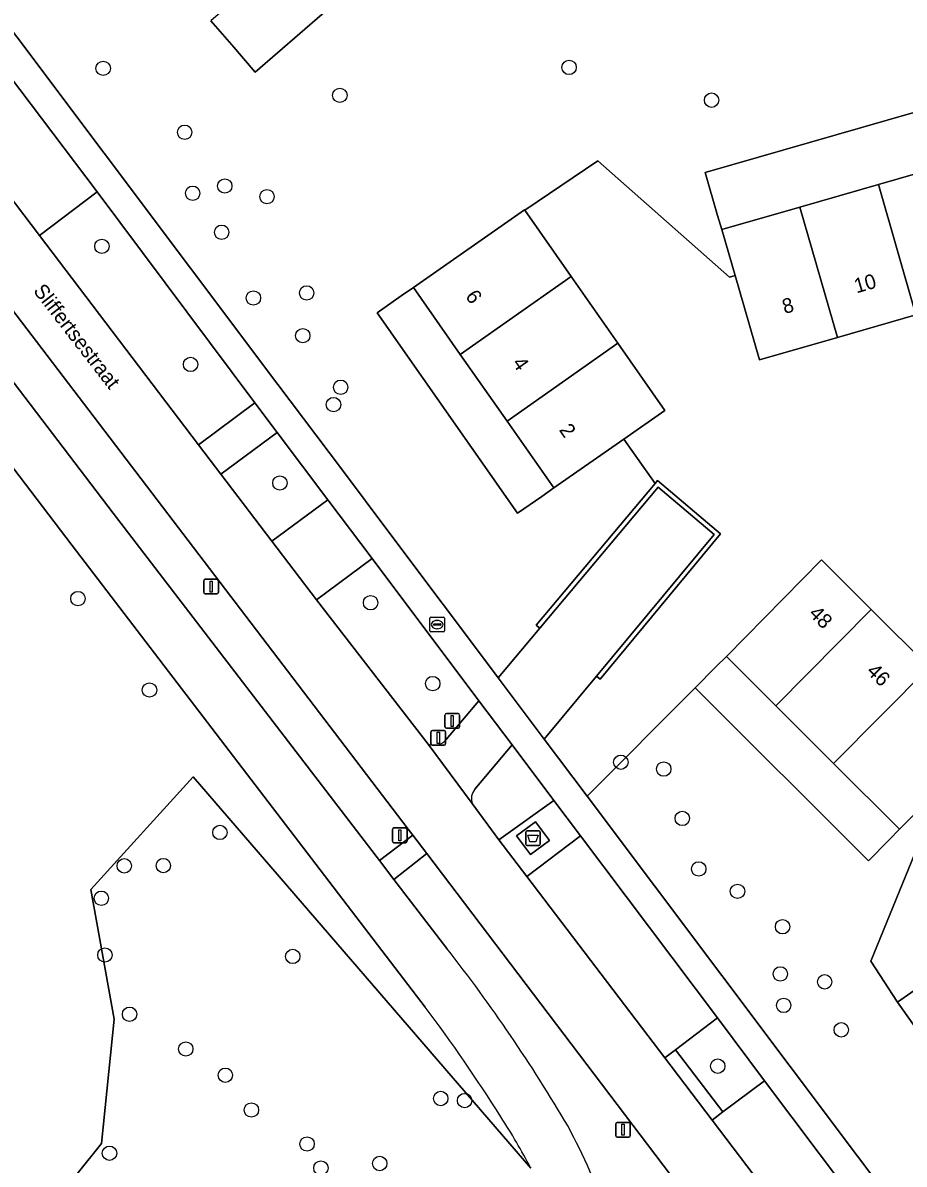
# Model space of a CAD drawing. Extents: x 156661 to 157576, y 383570 to 384425.
# Drawn here: x 156921.7 to 156981.6, y 384130.7 to 384208.3 of the extents above; entities that cross this region are included whole.
import ezdxf

# ---------------------------------------------------------------- set-up
doc = ezdxf.new("R2010")
doc.units = 0
for name, color, linetype in [('IMGEO_Afsluitpaal', 7, 'Continuous'), ('IMGEO_Afval_apart_plaats', 7, 'Continuous'), ('IMGEO_Berm_groen', 7, 'Continuous'), ('IMGEO_Berm_open', 7, 'Continuous'), ('IMGEO_Boom', 7, 'Continuous'), ('IMGEO_Brandkraan', 7, 'Continuous'), ('IMGEO_Erf', 7, 'Continuous'), ('IMGEO_Fietspad_gesloten', 7, 'Continuous'), ('IMGEO_Fietspad_open', 7, 'Continuous'), ('IMGEO_Groenvoorziening', 7, 'Continuous'), ('IMGEO_Lichtmast', 7, 'Continuous'), ('IMGEO_Muur', 7, 'Continuous'), ('IMGEO_Naaldbos', 7, 'Continuous'), ('IMGEO_Openbare_ruimte_label', 7, 'Continuous'), ('IMGEO_Pand', 7, 'Continuous'), ('IMGEO_Pand_nummerreeks', 7, 'Continuous'), ('IMGEO_Parkeervlak_open', 7, 'Continuous'), ('IMGEO_Rijbaan_lokaal_gesloten', 7, 'Continuous'), ('IMGEO_Rijbaan_lokaal_open', 7, 'Continuous'), ('IMGEO_Voetpad_gesloten', 7, 'Continuous'), ('IMGEO_Voetpad_open', 7, 'Continuous')]:
    doc.layers.add(name, color=color, linetype=linetype)

msp = doc.modelspace()

# ---------------------------------------------------------------- linework, layer by layer
at = {"layer": 'IMGEO_Afsluitpaal'}
for p, q in [((156950.378, 384160.425), (156950.378, 384161.225)), ((156950.378, 384161.225), (156950.378, 384160.425)), ((156950.478, 384161.325), (156951.268, 384161.325)), ((156951.268, 384161.325), (156950.478, 384161.325)), ((156951.368, 384161.225), (156951.368, 384160.425)), ((156951.368, 384160.425), (156951.368, 384161.225)), ((156949.428, 384159.276), (156949.428, 384160.076)), ((156949.428, 384160.076), (156949.428, 384159.276)), ((156949.528, 384160.176), (156950.318, 384160.176)), ((156950.318, 384160.176), (156949.528, 384160.176)), ((156950.418, 384160.076), (156950.418, 384159.276)), ((156950.418, 384159.276), (156950.418, 384160.076)), ((156951.268, 384160.325), (156950.478, 384160.325)), ((156950.478, 384160.325), (156951.268, 384160.325)), ((156950.318, 384159.176), (156949.528, 384159.176)), ((156949.528, 384159.176), (156950.318, 384159.176))]:
    msp.add_line(p, q, dxfattribs=at)
for points in [[(156950.798, 384161.2), (156950.948, 384161.2), (156950.948, 384160.45), (156950.798, 384160.45), (156950.798, 384161.2)], [(156949.848, 384160.051), (156949.998, 384160.051), (156949.998, 384159.301), (156949.848, 384159.301), (156949.848, 384160.051)]]:
    msp.add_lwpolyline(points, dxfattribs=at)
for centre, start, end in [((156950.478, 384161.225), 90, 180), ((156950.478, 384161.225), 90, 180), ((156951.268, 384161.225), 0, 90), ((156951.268, 384161.225), 360, 90), ((156949.528, 384160.076), 90, 180), ((156949.528, 384160.076), 90, 180), ((156950.318, 384160.076), 0, 90), ((156950.318, 384160.076), 360, 90), ((156950.478, 384160.425), 180, 270), ((156950.478, 384160.425), 180, 270), ((156951.268, 384160.425), 270, 0), ((156951.268, 384160.425), 270, 0), ((156949.528, 384159.276), 180, 270), ((156949.528, 384159.276), 180, 270), ((156950.318, 384159.276), 270, 0), ((156950.318, 384159.276), 270, 0)]:
    msp.add_arc(centre, 0.1, start, end, dxfattribs=at)
at = {"layer": 'IMGEO_Afval_apart_plaats'}
for p, q in [((156955.87, 384152.455), (156955.87, 384153.255)), ((156955.87, 384153.255), (156955.87, 384152.455)), ((156955.97, 384153.355), (156956.76, 384153.355)), ((156956.76, 384153.355), (156955.97, 384153.355)), ((156956.86, 384153.255), (156956.86, 384152.455)), ((156956.86, 384152.455), (156956.86, 384153.255)), ((156956.76, 384152.355), (156955.97, 384152.355)), ((156955.97, 384152.355), (156956.76, 384152.355))]:
    msp.add_line(p, q, dxfattribs=at)
msp.add_lwpolyline([(156956.013, 384153.069), (156956.717, 384153.069), (156956.568, 384152.599), (156956.162, 384152.599), (156956.013, 384153.069)], dxfattribs=at)
for centre, start, end in [((156955.97, 384153.255), 90, 180), ((156955.97, 384153.255), 90, 180), ((156956.76, 384153.255), 0, 90), ((156956.76, 384153.255), 360, 90), ((156955.97, 384152.455), 180, 270), ((156955.97, 384152.455), 180, 270), ((156956.76, 384152.455), 270, 0), ((156956.76, 384152.455), 270, 0)]:
    msp.add_arc(centre, 0.1, start, end, dxfattribs=at)
at = {"layer": 'IMGEO_Berm_groen'}
for points in [[(156867.867, 384253.653), (156927.81, 384174.952), (156945.927, 384151.336), (156948.198, 384153.058), (156947.883, 384153.474), (156869.636, 384256.091)], [(156945.427, 384171.858), (156941.651, 384169.047), (156949.248, 384159.24)], [(156950.46, 384159.552), (156952.69, 384162.198), (156945.427, 384171.858)], [(156949.137, 384151.82), (156946.909, 384150.056), (156950.51, 384145.361)], [(156967.768, 384127.243), (156949.137, 384151.82)]]:
    msp.add_lwpolyline(points, dxfattribs=at)
for points in [[(156926.719, 384196.787), (156922.806, 384193.826), (156933.628, 384179.594), (156937.458, 384182.455)], [(156938.971, 384180.443), (156935.139, 384177.608), (156938.611, 384173.044), (156942.416, 384175.861)], [(156968.907, 384140.631), (156966.06, 384138.467), (156969.272, 384134.245), (156972.116, 384136.364)]]:
    msp.add_lwpolyline(points, close=True, dxfattribs=at)
for centre, radius, start, end in [((156949.643, 384160.215), 1.052, 247.92674, 320.94521), ((156863.016, 384076.914), 111.087, 30.48417, 38.03635), ((156914.405, 384109.729), 50.202, 20.20282, 27.96194)]:
    msp.add_arc(centre, radius, start, end, dxfattribs=at)
at = {"layer": 'IMGEO_Berm_open'}
for points in [[(156952.237, 384155.208), (156954.053, 384152.742), (156957.791, 384155.414), (156954.942, 384159.203)], [(156954.942, 384159.203), (156952.419, 384156.18)]]:
    msp.add_lwpolyline(points, dxfattribs=at)
msp.add_lwpolyline([(156966.06, 384138.467), (156965.332, 384137.913), (156968.544, 384133.691), (156969.272, 384134.245)], close=True, dxfattribs=at)
msp.add_arc((156953.136, 384155.543), 0.959, 138.35735, 200.43181, dxfattribs=at)
at = {"layer": 'IMGEO_Boom'}
for centre in [(156927.137, 384205.187), (156958.823, 384205.253), (156943.231, 384203.351), (156968.508, 384203.025), (156932.682, 384200.841), (156933.225, 384196.695), (156935.408, 384197.187), (156938.277, 384196.465), (156935.194, 384194.045), (156927.052, 384193.089), (156940.974, 384189.92), (156937.352, 384189.576), (156940.71, 384187.014), (156933.08, 384185.058), (156943.289, 384183.506), (156942.799, 384182.327), (156939.154, 384176.999), (156925.421, 384169.139), (156945.323, 384168.861), (156949.547, 384163.361), (156930.289, 384162.926), (156962.338, 384158.019), (156965.255, 384157.552), (156966.515, 384154.196), (156935.074, 384153.242), (156928.573, 384150.974), (156931.227, 384150.992), (156967.635, 384150.763), (156970.271, 384149.242), (156927.015, 384148.769), (156973.336, 384146.834), (156927.256, 384144.91), (156940.03, 384144.813), (156973.183, 384143.624), (156976.199, 384143.087), (156973.412, 384141.488), (156928.933, 384140.884), (156977.328, 384139.827), (156932.757, 384138.524), (156968.927, 384137.355), (156935.445, 384136.739), (156950.091, 384135.159), (156951.715, 384135.019), (156937.217, 384134.378), (156927.57, 384131.437), (156941.002, 384132.065), (156945.945, 384130.737), (156941.942, 384130.43)]:
    msp.add_circle(centre, 0.489, dxfattribs=at)
at = {"layer": 'IMGEO_Brandkraan'}
for p, q in [((156949.35, 384166.948), (156949.35, 384167.8)), ((156949.425, 384167.874), (156950.277, 384167.874)), ((156949.838, 384167.654), (156949.863, 384167.654)), ((156950.351, 384167.8), (156950.351, 384166.948)), ((156950.277, 384166.874), (156949.425, 384166.874)), ((156949.609, 384167.368), (156949.609, 384167.38)), ((156950.047, 384167.331), (156949.649, 384167.331)), ((156949.652, 384167.417), (156950.05, 384167.417)), ((156949.861, 384167.094), (156949.836, 384167.094)), ((156950.093, 384167.38), (156950.093, 384167.368))]:
    msp.add_line(p, q, dxfattribs=at)
for points in [[(156949.35, 384166.948), (156949.35, 384167.8)], [(156949.425, 384167.874), (156950.277, 384167.874)], [(156950.351, 384167.8), (156950.351, 384166.948)], [(156950.277, 384166.874), (156949.425, 384166.874)]]:
    msp.add_lwpolyline(points, dxfattribs=at)
for centre, radius, start, end in [((156949.427, 384167.798), 0.0765, 91.55205, 178.44795), ((156949.427, 384167.798), 0.0765, 91.55205, 178.44795), ((156950.275, 384167.798), 0.0765, 1.55205, 88.44795), ((156950.275, 384167.798), 0.0765, 1.55205, 88.44795), ((156949.427, 384166.95), 0.0765, 181.55205, 268.44795), ((156949.427, 384166.95), 0.0765, 181.55205, 268.44795), ((156949.649, 384167.377), 0.0403, 85.87752, 175.75265), ((156949.646, 384167.367), 0.0366, 178.93798, 274.71019), ((156950.05, 384167.374), 0.043, 264.86636, 352.45326), ((156950.054, 384167.379), 0.0386, 1.73085, 96.63898), ((156950.275, 384166.95), 0.0765, 271.55205, 358.44795), ((156950.275, 384166.95), 0.0765, 271.55205, 358.44795)]:
    msp.add_arc(centre, radius, start, end, dxfattribs=at)
for centre, major_axis, ratio, start_param, end_param in [((156949.837, 384167.374), (-0.387, 0.002), 0.722429, 4.712389, 7.853982), ((156949.862, 384167.374), (-0.39, 0.002), 0.717154, 1.570796, 4.712389)]:
    msp.add_ellipse(centre, major_axis=major_axis, ratio=ratio, start_param=start_param, end_param=end_param, dxfattribs=at)
at = {"layer": 'IMGEO_Erf'}
for points in [[(156984.917, 384199.793), (156984.074, 384202.696), (156968.071, 384198.098), (156968.921, 384195.187), (156969.2, 384194.233), (156974.52, 384195.759), (156979.855, 384197.288), (156985.199, 384198.821)], [(156957.791, 384176.663), (156954.609, 384181.197), (156951.421, 384185.741), (156948.233, 384190.285), (156947.412, 384189.712), (156945.765, 384188.562), (156955.31, 384174.937), (156956.957, 384176.083)], [(156968.807, 384164.496), (156967.386, 384163.072), (156979.171, 384151.311), (156980.584, 384152.741), (156981.295, 384153.461), (156976.802, 384157.938), (156972.871, 384161.856), (156969.513, 384165.203)]]:
    msp.add_lwpolyline(points, close=True, dxfattribs=at)
for points in [[(156982.403, 384188.422), (156977.068, 384186.892), (156971.762, 384185.371), (156970.105, 384191.102), (156969.731, 384190.994), (156960.769, 384198.905), (156955.81, 384195.537), (156958.961, 384191.039), (156962.144, 384186.494), (156965.34, 384181.931), (156962.55, 384179.984), (156964.672, 384176.966), (156964.835, 384177.162), (156969.111, 384173.541), (156960.923, 384163.67), (156960.685, 384163.868), (156957.136, 384159.589), (156960.044, 384155.717), (156967.386, 384163.072), (156968.807, 384164.496), (156969.513, 384165.203), (156975.991, 384171.765), (156979.369, 384168.397), (156983.3, 384164.478)], [(156983.841, 384155.53), (156979.346, 384144.483), (156981.162, 384141.701), (156985.686, 384144.882)]]:
    msp.add_lwpolyline(points, dxfattribs=at)
at = {"layer": 'IMGEO_Fietspad_gesloten'}
for points in [[(156867.867, 384253.653), (156865.71, 384256.504), (156841.833, 384287.919), (156840.64, 384289.505), (156837.709, 384287.416), (156838.979, 384285.829), (156848.127, 384273.808), (156849.254, 384272.327), (156925.032, 384172.754), (156949.045, 384141.371)], [(156950.51, 384145.361), (156946.909, 384150.056), (156945.927, 384151.336), (156927.81, 384174.952), (156867.867, 384253.653)]]:
    msp.add_lwpolyline(points, dxfattribs=at)
for centre, radius, start, end in [((156863.016, 384076.914), 111.087, 30.48417, 38.03635), ((156855.827, 384071.678), 116.39, 32.31787, 36.78313), ((156917.342, 384110.12), 43.854, 27.58281, 32.83983), ((156914.405, 384109.729), 50.202, 20.20282, 27.96194)]:
    msp.add_arc(centre, radius, start, end, dxfattribs=at)
at = {"layer": 'IMGEO_Fietspad_open'}
msp.add_lwpolyline([(156949.137, 384151.82), (156948.198, 384153.058), (156945.927, 384151.336), (156946.909, 384150.056)], close=True, dxfattribs=at)
at = {"layer": 'IMGEO_Groenvoorziening'}
for points in [[(156949.045, 384141.371), (156925.032, 384172.754), (156849.254, 384272.327)], [(156879.806, 384262.53), (156939.02, 384183.696), (156943.34, 384177.955), (156946.64, 384173.562), (156953.814, 384164.012), (156954.003, 384163.76), (156956.828, 384167.129), (156956.591, 384167.328), (156964.672, 384176.966), (156962.55, 384179.984), (156957.791, 384176.663), (156956.957, 384176.083), (156955.31, 384174.937), (156945.765, 384188.562), (156947.412, 384189.712), (156948.233, 384190.285), (156955.782, 384195.577), (156955.81, 384195.537), (156960.769, 384198.905), (156969.731, 384190.994), (156970.105, 384191.102), (156969.2, 384194.233), (156968.921, 384195.187), (156968.071, 384198.098), (156984.074, 384202.696)], [(156949.633, 384215.464), (156937.483, 384204.932), (156935.882, 384206.783), (156934.463, 384208.423)], [(157023.4, 384139.952), (157007.655, 384134.505), (157006.661, 384137.356), (157006.33, 384138.305), (157004.719, 384142.893), (157004.101, 384142.683), (156998.668, 384146.731), (156998.209, 384146.407), (157000.083, 384143.732), (157000.656, 384142.92), (157002.388, 384140.459), (156988.79, 384130.883), (156987.061, 384133.355), (156986.487, 384134.177), (156981.162, 384141.701), (156979.346, 384144.483), (156983.841, 384155.53), (156983.601, 384155.776), (156981.295, 384153.461), (156980.584, 384152.741), (156979.171, 384151.311), (156967.386, 384163.072), (156960.044, 384155.717), (156983.009, 384125.143)], [(156927.02, 384132.097), (156927.884, 384140.558), (156926.305, 384149.362), (156933.269, 384157.022), (156956.212, 384130.426)], [(156912.976, 384107.464), (156913.505, 384107.329), (156913.922, 384107.261), (156914.342, 384107.209), (156942.127, 384113.492), (156930.191, 384114.906), (156914.869, 384116.99), (156927.02, 384132.097)]]:
    msp.add_lwpolyline(points, dxfattribs=at)
for centre, radius, start, end in [((156855.827, 384071.678), 116.39, 32.31787, 36.78313), ((156917.342, 384110.12), 43.854, 27.58281, 32.83983)]:
    msp.add_arc(centre, radius, start, end, dxfattribs=at)
at = {"layer": 'IMGEO_Lichtmast'}
for p, q in [((156933.985, 384169.554), (156933.985, 384170.354)), ((156933.985, 384170.354), (156933.985, 384169.554)), ((156934.085, 384170.454), (156934.875, 384170.454)), ((156934.875, 384170.454), (156934.085, 384170.454)), ((156934.975, 384170.354), (156934.975, 384169.554)), ((156934.975, 384169.554), (156934.975, 384170.354)), ((156934.875, 384169.454), (156934.085, 384169.454)), ((156934.085, 384169.454), (156934.875, 384169.454)), ((156946.812, 384152.648), (156946.812, 384153.448)), ((156946.812, 384153.448), (156946.812, 384152.648)), ((156946.912, 384153.548), (156947.702, 384153.548)), ((156947.702, 384153.548), (156946.912, 384153.548)), ((156947.802, 384153.448), (156947.802, 384152.648)), ((156947.802, 384152.648), (156947.802, 384153.448)), ((156947.702, 384152.548), (156946.912, 384152.548)), ((156946.912, 384152.548), (156947.702, 384152.548)), ((156962.094, 384133.529), (156962.884, 384133.529)), ((156962.884, 384133.529), (156962.094, 384133.529)), ((156961.994, 384132.629), (156961.994, 384133.429)), ((156961.994, 384133.429), (156961.994, 384132.629)), ((156962.984, 384133.429), (156962.984, 384132.629)), ((156962.984, 384132.629), (156962.984, 384133.429)), ((156962.884, 384132.529), (156962.094, 384132.529)), ((156962.094, 384132.529), (156962.884, 384132.529))]:
    msp.add_line(p, q, dxfattribs=at)
for points in [[(156934.405, 384170.329), (156934.555, 384170.329), (156934.555, 384169.579), (156934.405, 384169.579), (156934.405, 384170.329)], [(156947.232, 384153.423), (156947.382, 384153.423), (156947.382, 384152.673), (156947.232, 384152.673), (156947.232, 384153.423)], [(156962.414, 384133.404), (156962.564, 384133.404), (156962.564, 384132.654), (156962.414, 384132.654), (156962.414, 384133.404)]]:
    msp.add_lwpolyline(points, dxfattribs=at)
for centre, start, end in [((156934.085, 384170.354), 90, 180), ((156934.085, 384170.354), 90, 180), ((156934.875, 384170.354), 0, 90), ((156934.875, 384170.354), 360, 90), ((156934.085, 384169.554), 180, 270), ((156934.085, 384169.554), 180, 270), ((156934.875, 384169.554), 270, 0), ((156934.875, 384169.554), 270, 0), ((156946.912, 384153.448), 90, 180), ((156946.912, 384153.448), 90, 180), ((156947.702, 384153.448), 0, 90), ((156947.702, 384153.448), 360, 90), ((156946.912, 384152.648), 180, 270), ((156946.912, 384152.648), 180, 270), ((156947.702, 384152.648), 270, 0), ((156947.702, 384152.648), 270, 0), ((156962.094, 384133.429), 90, 180), ((156962.094, 384133.429), 90, 180), ((156962.884, 384133.429), 0, 90), ((156962.884, 384133.429), 360, 90), ((156962.094, 384132.629), 180, 270), ((156962.094, 384132.629), 180, 270), ((156962.884, 384132.629), 270, 0), ((156962.884, 384132.629), 270, 0)]:
    msp.add_arc(centre, 0.1, start, end, dxfattribs=at)
at = {"layer": 'IMGEO_Muur'}
for points in [[(156984.917, 384199.793), (156984.074, 384202.696), (156968.071, 384198.098), (156968.921, 384195.187)], [(156969.2, 384194.233), (156968.921, 384195.187)], [(156948.233, 384190.285), (156947.412, 384189.712)], [(156947.412, 384189.712), (156945.765, 384188.562), (156955.31, 384174.937), (156956.957, 384176.083)], [(156956.957, 384176.083), (156957.791, 384176.663)], [(156967.386, 384163.072), (156968.807, 384164.496)], [(156968.807, 384164.496), (156969.513, 384165.203)], [(156980.584, 384152.741), (156979.171, 384151.311), (156967.386, 384163.072)], [(156981.295, 384153.461), (156980.584, 384152.741)]]:
    msp.add_lwpolyline(points, dxfattribs=at)
msp.add_lwpolyline([(156956.591, 384167.328), (156956.828, 384167.129), (156964.873, 384176.724), (156968.677, 384173.502), (156960.685, 384163.868), (156960.923, 384163.67), (156969.111, 384173.541), (156964.835, 384177.162), (156964.672, 384176.966)], close=True, dxfattribs=at)
at = {"layer": 'IMGEO_Naaldbos'}
msp.add_lwpolyline([(156956.212, 384130.426), (156933.269, 384157.022), (156926.305, 384149.362), (156927.884, 384140.558), (156927.02, 384132.097), (156914.869, 384116.99), (156930.191, 384114.906), (156942.127, 384113.492), (156960.908, 384117.741), (156959.31, 384122.816)], dxfattribs=at)
at = {"layer": 'IMGEO_Pand'}
for points in [[(156934.463, 384208.423), (156935.882, 384206.783), (156937.483, 384204.932), (156949.633, 384215.464), (156949.708, 384215.53), (156946.692, 384219.014)], [(156982.403, 384188.422), (156987.761, 384189.959), (156986.086, 384195.753), (156985.199, 384198.821), (156979.855, 384197.288)], [(156974.52, 384195.759), (156977.068, 384186.892), (156982.403, 384188.422), (156979.855, 384197.288)], [(156958.961, 384191.039), (156955.81, 384195.537), (156955.782, 384195.577), (156948.233, 384190.285), (156951.421, 384185.741)], [(156974.52, 384195.759), (156969.2, 384194.233), (156970.105, 384191.102), (156971.762, 384185.371), (156977.068, 384186.892)], [(156958.961, 384191.039), (156951.421, 384185.741), (156954.609, 384181.197), (156962.144, 384186.494)], [(156954.609, 384181.197), (156957.791, 384176.663), (156962.55, 384179.984), (156965.34, 384181.931), (156962.144, 384186.494)], [(156979.369, 384168.397), (156975.991, 384171.765), (156969.513, 384165.203), (156972.871, 384161.856)], [(156979.369, 384168.397), (156972.871, 384161.856), (156976.802, 384157.938), (156983.3, 384164.478)], [(156983.3, 384164.478), (156976.802, 384157.938), (156981.295, 384153.461), (156983.601, 384155.776), (156987.799, 384159.993)], [(156990.988, 384137.34), (156985.686, 384144.882), (156981.162, 384141.701), (156986.487, 384134.177)]]:
    msp.add_lwpolyline(points, close=True, dxfattribs=at)
at = {"layer": 'IMGEO_Parkeervlak_open'}
for points in [[(156926.719, 384196.787), (156920.708, 384204.77), (156916.761, 384201.782), (156922.806, 384193.826)], [(156933.628, 384179.594), (156935.139, 384177.608), (156938.971, 384180.443), (156937.458, 384182.455)], [(156941.651, 384169.047), (156945.427, 384171.858), (156942.416, 384175.861), (156938.611, 384173.044)], [(156959.593, 384153.019), (156955.947, 384150.252), (156965.332, 384137.913), (156966.06, 384138.467), (156968.907, 384140.631)], [(156972.116, 384136.364), (156969.272, 384134.245), (156968.544, 384133.691), (156976.126, 384123.722), (156979.61, 384126.397)]]:
    msp.add_lwpolyline(points, close=True, dxfattribs=at)
at = {"layer": 'IMGEO_Rijbaan_lokaal_gesloten'}
for points in [[(156876.48, 384254.755), (156868.186, 384265.651), (156860.937, 384275.173), (156857.345, 384272.328), (156868.344, 384257.78), (156869.636, 384256.091), (156947.883, 384153.474), (156948.198, 384153.058), (156949.137, 384151.82), (156967.768, 384127.243)], [(156978.939, 384120.025), (156978.024, 384121.227), (156977.753, 384121.583), (156976.126, 384123.722), (156968.544, 384133.691), (156965.332, 384137.913), (156955.947, 384150.252), (156954.053, 384152.742), (156952.237, 384155.208), (156949.248, 384159.24), (156941.651, 384169.047), (156938.611, 384173.044), (156935.139, 384177.608), (156933.628, 384179.594), (156922.806, 384193.826), (156916.761, 384201.782), (156914.397, 384204.906), (156905.044, 384217.212), (156901.645, 384221.683), (156891.001, 384235.643), (156888.996, 384238.303), (156878.44, 384252.173), (156876.735, 384254.42)]]:
    msp.add_lwpolyline(points, dxfattribs=at)
at = {"layer": 'IMGEO_Rijbaan_lokaal_open'}
msp.add_lwpolyline([(156968.677, 384173.502), (156964.873, 384176.724), (156956.828, 384167.129), (156954.003, 384163.76), (156957.136, 384159.589), (156960.685, 384163.868)], close=True, dxfattribs=at)
for points in [[(156954.942, 384159.203), (156952.69, 384162.198), (156950.46, 384159.552)], [(156949.248, 384159.24), (156952.237, 384155.208)], [(156952.419, 384156.18), (156954.942, 384159.203)]]:
    msp.add_lwpolyline(points, dxfattribs=at)
for centre, radius, start, end in [((156949.643, 384160.215), 1.052, 247.92674, 320.94521), ((156953.136, 384155.543), 0.959, 138.35735, 200.43181)]:
    msp.add_arc(centre, radius, start, end, dxfattribs=at)
at = {"layer": 'IMGEO_Voetpad_gesloten'}
msp.add_lwpolyline([(156956.529, 384153.975), (156955.246, 384153.023), (156956.202, 384151.735), (156957.484, 384152.687)], close=True, dxfattribs=at)
at = {"layer": 'IMGEO_Voetpad_open'}
for points in [[(156983.009, 384125.143), (156960.044, 384155.717), (156957.136, 384159.589), (156954.003, 384163.76), (156953.814, 384164.012), (156946.64, 384173.562), (156943.34, 384177.955), (156939.02, 384183.696), (156879.806, 384262.53), (156876.187, 384267.345), (156852.753, 384298.627)], [(156852.393, 384295.853), (156865.294, 384278.622), (156874.701, 384266.057), (156878.321, 384261.237), (156882.665, 384255.414), (156893.129, 384241.435), (156895.163, 384238.727), (156905.644, 384224.752), (156909.04, 384220.251), (156918.348, 384207.896), (156920.708, 384204.77), (156926.719, 384196.787), (156937.458, 384182.455), (156938.971, 384180.443), (156942.416, 384175.861), (156945.427, 384171.858), (156952.69, 384162.198), (156954.942, 384159.203), (156957.791, 384155.414), (156959.593, 384153.019), (156968.907, 384140.631), (156972.116, 384136.364), (156979.61, 384126.397)]]:
    msp.add_lwpolyline(points, dxfattribs=at)
for points in [[(156959.593, 384153.019), (156957.791, 384155.414), (156954.053, 384152.742), (156955.947, 384150.252)], [(156955.246, 384153.023), (156956.529, 384153.975), (156957.484, 384152.687), (156956.202, 384151.735)]]:
    msp.add_lwpolyline(points, close=True, dxfattribs=at)

# ---------------------------------------------------------------- texts
at = {"layer": 'IMGEO_Openbare_ruimte_label'}
msp.add_text('Sliffertsestraat', height=1, rotation=307.80965, dxfattribs=at).set_placement((156922.339, 384190.051))
at = {"layer": 'IMGEO_Pand_nummerreeks'}
for s, rotation, p in [('10', 16.00116, (156978.366, 384189.886)), ('6', 305.05514, (156951.729, 384189.69)), ('8', 16.00116, (156973.476, 384188.484)), ('4', 305.05514, (156954.918, 384185.144)), ('2', 305.05514, (156958.104, 384180.603)), ('48', 315.08881, (156975.062, 384168.059)), ('46', 315.08881, (156978.996, 384164.137))]:
    msp.add_text(s, height=1, rotation=rotation, dxfattribs=at).set_placement(p)

doc.saveas('drawing.dxf')
